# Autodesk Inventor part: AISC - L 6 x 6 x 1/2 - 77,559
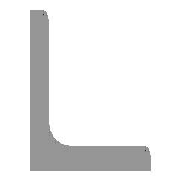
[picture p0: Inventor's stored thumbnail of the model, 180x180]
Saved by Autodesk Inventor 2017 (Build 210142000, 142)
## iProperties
Created: 2016-02
Part Number: AISC - L 6 x 6 x 1/2 - 77,559
Material: Stal, miękka
Description: Kątownik
Document SubType Name: Modeling
Standard: ANSI
Designer: X
Standards Organization: ANSI
Language: pl-PL
Size Designation: L 6 x 6 x 1/2
Categories: <MemberInstance><Categories><Category DisplayName="Kształtowniki konstrukcyjne" InternalName="089c4875-fa83-4c05-b084-43b9cc11f5ed" Mnemonic="GRDR"><CategoryPar
Stock Number: L 6 x 6 x 1/2
Density: 7.85 g/cm^3
Appearance: Częściowo polerowana
_CCFamilyMember: 47
_CCFamilyDisplayName: ANSI L (Kątownik równoramienny) - Kątownik — Rozmiary w nawiasach zostały wycofane
_FrameMemberDoc: Frame Member File
_Version: 15.0.0
_GetPNFromCC: 1
IsCustomPart: 1
Author: X
G_L: 1970,000 mm
G_W: 152,400 mm
G_H: 152,400 mm
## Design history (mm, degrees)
node "Płaszczyzna początkowa"
node "Płaszczyzna końcowa"
sketch "Szkic"
  geometry: L1 (152.4, 0)-(0, 0); L2 (0, 0)-(0, 152.4); L3 (0, 152.4)-(6.35, 152.4); L4 (12.7, 146.05)-(12.7, 25.4); L5 (25.4, 12.7)-(146.05, 12.7); L6 (152.4, 6.35)-(152.4, 0); L7 (0, -11.041)-(0, 31.538); L8 (-11.041, 0)-(31.538, 0); L9 (0, 186.666)-(0, -43.993) reference; L10 (-43.993, 0)-(186.666, 0) reference; A1 r 12.7 centre (25.4, 25.4) between (12.7, 25.4) and (25.4, 12.7); A2 r 6.35 centre (6.35, 146.05) between (12.7, 146.05) and (6.35, 152.4); A3 r 6.35 centre (146.05, 6.35) between (152.4, 6.35) and (146.05, 12.7); 3 further points
  constraints: 16 end point, 6 point on circle, 6 point on line, 6 tangent, 4 parallel, 3 centre point, 2 collinear, 1 equal radius, 1 horizontal, 1 perpendicular
  dimensions: "d0" = 152.4 distance between parallel lines of L6 L2 (= G_H); "d1" = 152.4 distance between parallel lines of L3 L1 (= G_H); "d2" = 12.7 distance between parallel lines of L2 L4 (= G_T); "d3" = 12.7 distance between parallel lines of L1 L5 (= G_T); "d10" = 0 distance between parallel lines of L7 L2 (computed from ex); "d11" = 0 distance between parallel lines of L8 L1 (computed from d10); "d14" = 12.7 radius of A1 (= G_IR); "d15" = 6.35 radius of A2 (= G_ER)
extrude "Bryła" new body sketch "Szkic" stored distance "d4" = 1970 (= G_L); taper "d5" = 0 deg
node "Driven Length"
  sketch "Sketch3"
    geometry: L1 (0, 0)-(10, 0) reference
    constraints: 2 end point, 1 horizontal
  workplane "Work Plane3"
  sketch "Sketch4"
    geometry: L1 (-2, 0)-(12, 0) reference; L2 (-2, 1970)-(12, 1970) reference
    dimensions: "d17" = 1970 distance between parallel lines of L1 L2 (derived)
body "Solid1"
other parameters: "G_H" = 152.4 [user parameter; used in 2 equation terms], "G_T" = 12.7 [user parameter; used in 2 equation terms], "G_ER" = 6.35 [user parameter; used in 1 equation term], "G_IR" = 12.7 [user parameter; used in 1 equation term], "G_L" = 1970 (= d17) [user parameter; used in 1 equation term], "ex" = 0 [user parameter; used in 1 equation term], "G_OFFSET_START" = 0 [user parameter; used in 1 equation term], "G_OFFSET_END" = 0 [user parameter; used in 1 equation term], "d12" = 0 (computed from G_OFFSET_START), "d16" = 90 deg, "MAS" = 2.9168 [user parameter]
